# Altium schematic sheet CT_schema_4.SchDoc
size 278 x 170 mm
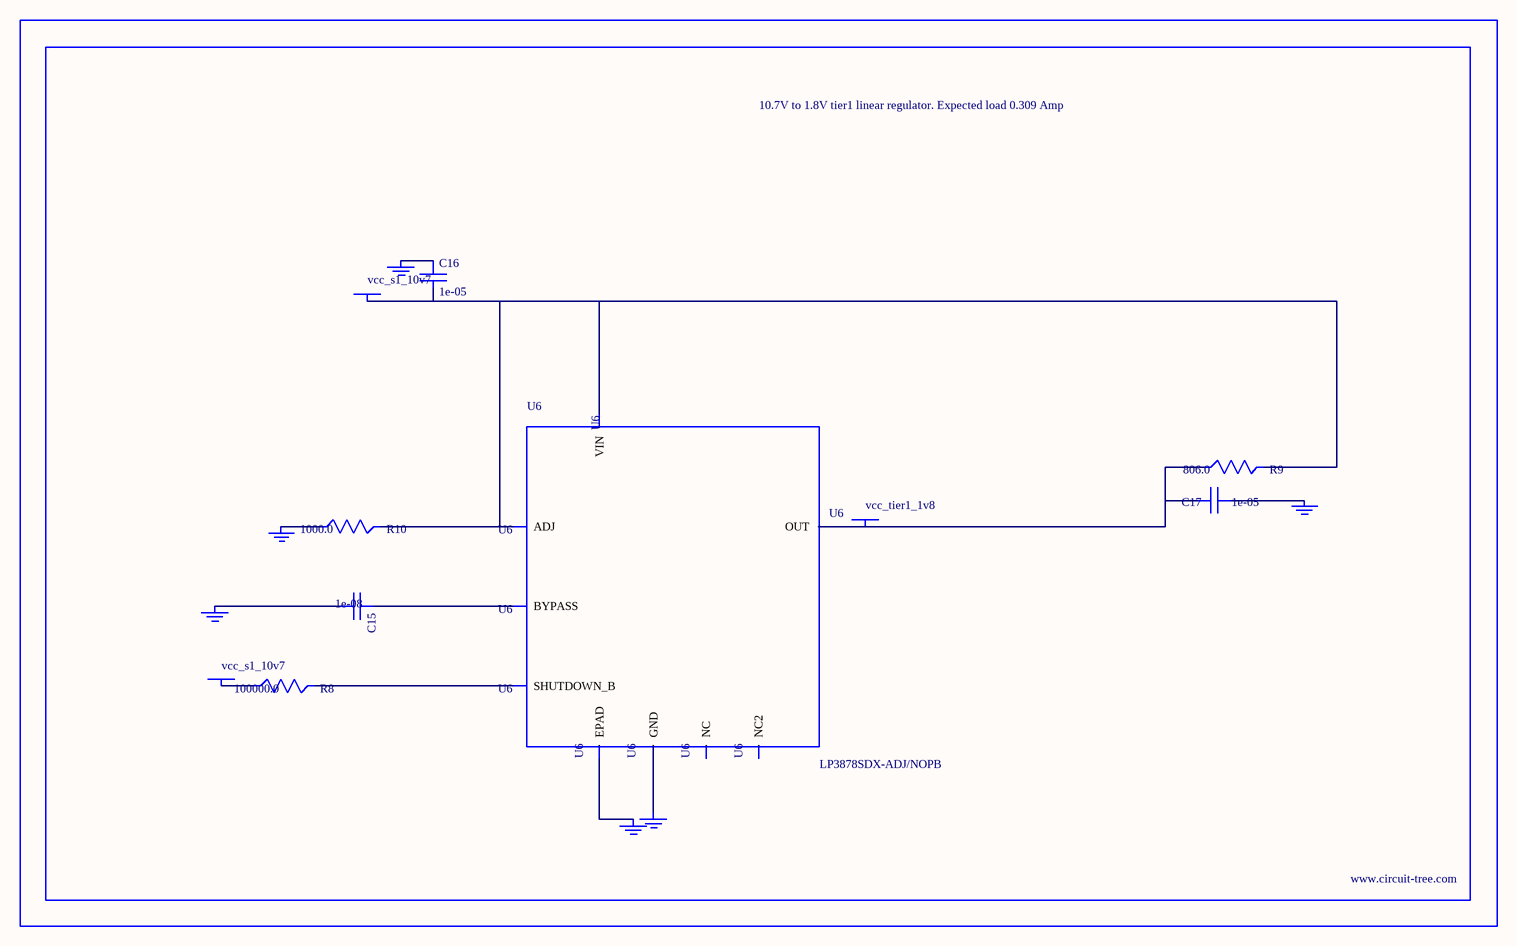
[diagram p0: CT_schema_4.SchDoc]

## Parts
BORDER3  (no value)
C15  1e-08  [C0402]
C16  1e-05  [C1206]
C17  1e-05  [C0805]
GND_INSTANCE_3_0  (no value)
GND_INSTANCE_3_1  (no value)
GND_INSTANCE_3_2  (no value)
GND_INSTANCE_3_3  (no value)
GND_INSTANCE_3_4  (no value)
GND_INSTANCE_3_5  (no value)
POWER_INSTANCE_3_0  vcc_s1_10v7
POWER_INSTANCE_3_1  vcc_s1_10v7
POWER_INSTANCE_3_2  vcc_tier1_1v8
R8  100000.0  [R0603]
R9  806.0  [R0603]
R10  1000.0  [R0603]
U6  LP3878SDX-ADJ/NOPB  [WSON-8]

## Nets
NetC15_1: C15.1 U6.1(BYPASS)
NetC15_2: C15.2 GND_INSTANCE_3_0.0(GND)
NetC16_1: C16.1 GND_INSTANCE_3_1.0(GND)
NetC16_2: C16.2 POWER_INSTANCE_3_0.0(PWR) R9.2 R10.2 U6.4(VIN) U6.6(ADJ)
NetC17_1: C17.1 GND_INSTANCE_3_2.0(GND)
NetC17_2: C17.2 POWER_INSTANCE_3_2.0(PWR) R9.1 U6.5(OUT)
NetGND_INSTANCE_3_3_0: GND_INSTANCE_3_3.0(GND) R10.1
NetGND_INSTANCE_3_4_0: GND_INSTANCE_3_4.0(GND) U6.PAD(EPAD)
NetGND_INSTANCE_3_5_0: GND_INSTANCE_3_5.0(GND) U6.3(GND)
NetPOWER_INSTANCE_3_1_0: POWER_INSTANCE_3_1.0(PWR) R8.1
NetR8_2: R8.2 U6.8(SHUTDOWN_B)

Not connected (* = marked no-connect by the designer): U6 2(NC) 7(NC2)

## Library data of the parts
BORDER3 = BORDER_PAGE3
C15 = C0402C103K3RAC
C16 = C1206C106K3RACTU
C17 = GRM219R60J106ME19D
GND_INSTANCE_3_0-GND_INSTANCE_3_5 = GND
POWER_INSTANCE_3_0-POWER_INSTANCE_3_2 = PWR
R8 = RC0603JR-07100KL
R9 = ERJ-3EKF8060V
R10 = RC0603JR-071KL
